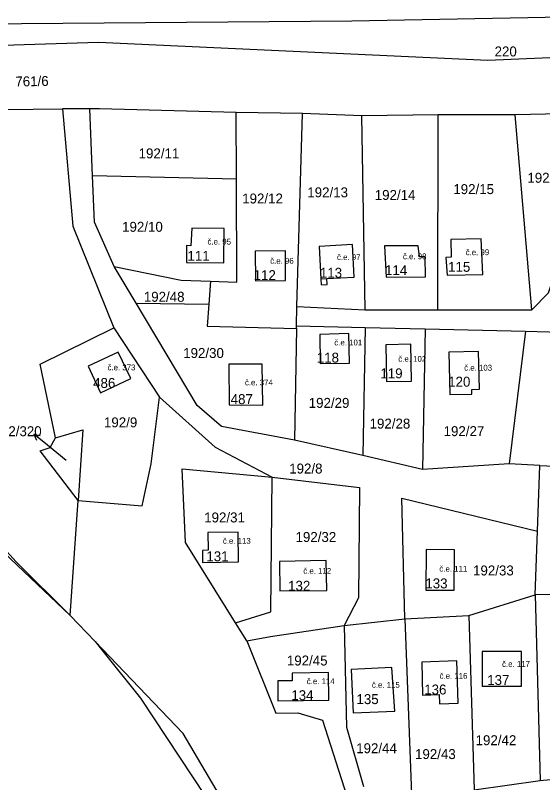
# Model space of a CAD drawing. Extents: x -887272 to -877616, y -1026687 to -1019819.
# Drawn here: x -882553.8 to -882463.7, y -1024170.3 to -1024039.2 of the extents above; entities that cross this region are included whole.
import ezdxf

# ---------------------------------------------------------------- set-up
doc = ezdxf.new("R2010")
doc.units = 0
for name, color, linetype in [('Definiční body', 7, 'Continuous'), ('Hranice parcel', 7, 'Continuous'), ('Parcelní čísla', 7, 'Continuous'), ('Polygon budovy', 7, 'Continuous'), ('Pop  PČ popisy', 7, 'Continuous'), ('Vnitřní kresba', 7, 'Continuous')]:
    doc.layers.add(name, color=color, linetype=linetype)

msp = doc.modelspace()

# ---------------------------------------------------------------- linework, layer by layer
at = {"layer": 'Hranice parcel'}
for p, q in [((-882541.07, -1024055.16), (-882545.75, -1024055.18)), ((-882545.75, -1024055.18), (-882543.98, -1024075.25)), ((-882539.38, -1024055.15), (-882541.07, -1024055.16)), ((-882540.58, -1024066.64), (-882541.07, -1024055.16)), ((-882516.06, -1024055.78), (-882539.38, -1024055.15)), ((-882516.01, -1024067.18), (-882516.06, -1024055.78)), ((-882504.74, -1024055.95), (-882516.06, -1024055.78)), ((-882505.7, -1024088.95), (-882504.74, -1024055.95)), ((-882494.61, -1024056.37), (-882504.74, -1024055.95)), ((-882481.56, -1024056.23), (-882494.61, -1024056.37)), ((-882494.01, -1024089.53), (-882494.61, -1024056.37)), ((-882481.6, -1024089.53), (-882481.56, -1024056.23)), ((-882468.38, -1024056.21), (-882481.56, -1024056.23)), ((-882459.39, -1024055.99), (-882468.38, -1024056.21)), ((-882465.58, -1024089.52), (-882468.38, -1024056.21)), ((-882516.01, -1024067.18), (-882540.58, -1024066.64)), ((-882543.98, -1024075.25), (-882536.95, -1024092.63)), ((-882533.15, -1024088.37), (-882536.9, -1024082.1)), ((-882520.44, -1024084.62), (-882520.72, -1024088.57)), ((-882533.15, -1024088.37), (-882520.72, -1024088.57)), ((-882505.74, -1024092.24), (-882505.7, -1024088.95)), ((-882505.7, -1024088.95), (-882494.01, -1024089.53)), ((-882494.01, -1024089.53), (-882481.6, -1024089.53)), ((-882481.6, -1024089.53), (-882465.58, -1024089.52)), ((-882536.95, -1024092.63), (-882529.15, -1024104.45)), ((-882505.75, -1024092.74), (-882506.08, -1024111.82)), ((-882505.75, -1024092.74), (-882505.74, -1024092.24)), ((-882505.74, -1024092.24), (-882494.04, -1024092.52)), ((-882494.04, -1024092.52), (-882494.44, -1024114.44)), ((-882494.04, -1024092.52), (-882483.75, -1024092.77)), ((-882483.75, -1024092.77), (-882484.26, -1024116.81)), ((-882483.75, -1024092.77), (-882466.65, -1024093.19)), ((-882466.65, -1024093.19), (-882469.42, -1024115.86)), ((-882466.65, -1024093.19), (-882458.6, -1024093.38)), ((-882494.44, -1024114.44), (-882506.08, -1024111.82)), ((-882543.07, -1024122.14), (-882549.54, -1024113.64)), ((-882484.26, -1024116.81), (-882494.44, -1024114.44)), ((-882469.42, -1024115.86), (-882484.26, -1024116.81)), ((-882464.18, -1024116.13), (-882469.42, -1024115.86)), ((-882464.6, -1024127.37), (-882464.18, -1024116.13)), ((-882464.18, -1024116.13), (-882447.68, -1024116.83)), ((-882544.44, -1024141.78), (-882543.07, -1024122.14)), ((-882465, -1024138.24), (-882464.6, -1024127.37)), ((-882544.44, -1024141.78), (-882553.65, -1024132.6)), ((-882476.32, -1024141.77), (-882465, -1024138.24)), ((-882453.49, -1024138.14), (-882465, -1024138.24)), ((-882465, -1024138.24), (-882464.13, -1024169.99)), ((-882544.44, -1024141.78), (-882540.14, -1024146.21)), ((-882487.23, -1024142.35), (-882476.32, -1024141.77)), ((-882476.32, -1024141.77), (-882475.42, -1024171.58)), ((-882514.25, -1024146.09), (-882516.17, -1024143.02)), ((-882497.59, -1024143.48), (-882487.23, -1024142.35)), ((-882487.23, -1024142.35), (-882486.14, -1024172.29)), ((-882508.92, -1024156.33), (-882500.23, -1024156.21)), ((-882464.13, -1024169.99), (-882453.52, -1024168.83)), ((-882475.42, -1024171.58), (-882464.13, -1024169.99))]:
    msp.add_line(p, q, dxfattribs=at)
for points in [[(-882445.26, -1024039.2), (-882496.32, -1024040.18), (-882559.82, -1024040.7), (-882602.37, -1024040.09)], [(-882603.02, -1024045.76), (-882539.56, -1024043.76), (-882473.06, -1024046.88), (-882408.1, -1024044.08), (-882339.94, -1024043.02), (-882340.1, -1024040.68)], [(-882731.42, -1024055.06), (-882680.72, -1024056.68), (-882649.26, -1024056.02), (-882607.88, -1024055.44), (-882600.66, -1024055.78), (-882545.75, -1024055.18)], [(-882465.58, -1024089.52), (-882462.72, -1024086.61), (-882455.48, -1024065.24), (-882459.39, -1024055.99)], [(-882536.9, -1024082.1), (-882540.24, -1024074.53), (-882540.58, -1024066.64)], [(-882520.44, -1024084.62), (-882515.93, -1024084.81), (-882516.01, -1024067.18)], [(-882524.56, -1024081.44), (-882518.16, -1024081.48), (-882518.1, -1024075.64), (-882523.66, -1024075.58), (-882523.8, -1024078.58), (-882524.56, -1024078.52), (-882524.56, -1024081.44)], [(-882473.94, -1024083.48), (-882474.19, -1024077.39), (-882479.39, -1024077.49), (-882479.33, -1024080.54), (-882480.23, -1024080.56), (-882480.04, -1024083.6), (-882473.94, -1024083.48)], [(-882495.9, -1024083.92), (-882496.2, -1024078.39), (-882501.88, -1024078.72), (-882501.59, -1024084.22), (-882501.54, -1024085.24), (-882500.52, -1024085.19), (-882500.58, -1024084.17), (-882495.9, -1024083.92)], [(-882490.46, -1024083.96), (-882483.72, -1024083.86), (-882483.76, -1024080.46), (-882484.76, -1024080.47), (-882485, -1024078.58), (-882490.72, -1024078.6), (-882490.46, -1024083.96)], [(-882507.66, -1024079.44), (-882512.81, -1024079.48), (-882512.77, -1024084.58), (-882507.62, -1024084.54), (-882507.66, -1024079.44)], [(-882536.9, -1024082.1), (-882525.45, -1024084.46), (-882520.44, -1024084.62)], [(-882506.08, -1024111.82), (-882518.58, -1024109.48), (-882522.71, -1024105.86), (-882533.15, -1024088.37)], [(-882520.72, -1024088.57), (-882520.99, -1024092.32), (-882505.75, -1024092.74)], [(-882546.91, -1024111.39), (-882549.52, -1024098.83), (-882536.95, -1024092.63)], [(-882501.79, -1024093.72), (-882501.71, -1024098.72), (-882496.72, -1024098.62), (-882496.79, -1024093.56), (-882501.79, -1024093.72)], [(-882490.39, -1024101.79), (-882486.14, -1024101.72), (-882486.24, -1024095.42), (-882490.49, -1024095.49), (-882490.39, -1024101.79)], [(-882534.06, -1024101.25), (-882536.19, -1024096.74), (-882541.31, -1024099.15), (-882539.22, -1024103.69), (-882534.06, -1024101.25)], [(-882479.73, -1024096.77), (-882479.54, -1024104.02), (-882475.79, -1024103.92), (-882475.81, -1024103.12), (-882474.51, -1024103.09), (-882474.68, -1024096.64), (-882479.73, -1024096.77)], [(-882511.53, -1024105.84), (-882511.6, -1024098.82), (-882517.29, -1024098.81), (-882517.24, -1024105.79), (-882511.53, -1024105.84)], [(-882543.07, -1024122.14), (-882532.14, -1024123), (-882530.59, -1024115.87), (-882529.15, -1024104.45)], [(-882529.15, -1024104.45), (-882519.64, -1024113.02), (-882509.9, -1024118.11)], [(-882546.91, -1024111.39), (-882542.24, -1024110.04), (-882543.07, -1024122.14)], [(-882549.54, -1024113.64), (-882547.84, -1024113.05), (-882546.91, -1024111.39)], [(-882553.65, -1024132.6), (-882563.04, -1024122.28), (-882568.27, -1024116.52), (-882569.89, -1024114.84), (-882570.12, -1024114.61)], [(-882570.12, -1024114.61), (-882568.22, -1024119.18), (-882544.44, -1024141.78)], [(-882516.17, -1024143.02), (-882524.72, -1024129.29), (-882525.26, -1024116.69), (-882509.9, -1024118.11)], [(-882516.17, -1024143.02), (-882510.14, -1024141.13), (-882509.9, -1024118.11)], [(-882509.9, -1024118.11), (-882495.01, -1024119.89), (-882495.16, -1024138.72), (-882497.59, -1024143.48)], [(-882487.23, -1024142.35), (-882487.75, -1024121.7), (-882464.6, -1024127.37)], [(-882520.83, -1024130.58), (-882521.83, -1024130.65), (-882521.8, -1024132.7), (-882515.65, -1024132.6), (-882515.73, -1024127.5), (-882520.88, -1024127.58), (-882520.83, -1024130.58)], [(-882478.8, -1024137.46), (-882478.76, -1024130.54), (-882483.62, -1024130.51), (-882483.66, -1024137.43), (-882478.8, -1024137.46)], [(-882500.57, -1024137.5), (-882500.66, -1024132.35), (-882508.66, -1024132.51), (-882508.62, -1024137.56), (-882500.57, -1024137.5)], [(-882514.25, -1024146.09), (-882510.19, -1024145.38), (-882497.59, -1024143.48)], [(-882497.59, -1024143.48), (-882497.2, -1024160.85), (-882494.31, -1024171)], [(-882501.82, -1024208.81), (-882505.78, -1024194.82), (-882525.14, -1024161.92), (-882540.14, -1024146.21)], [(-882540.14, -1024146.21), (-882538.86, -1024147.89), (-882532.4, -1024155.87), (-882516.84, -1024179.4), (-882505.08, -1024201.85), (-882501.82, -1024208.81)], [(-882514.25, -1024146.09), (-882509.29, -1024158.43), (-882505.52, -1024158.39), (-882501.29, -1024159.64), (-882495.81, -1024176.89), (-882492.56, -1024176.88)], [(-882474.02, -1024147.92), (-882474.02, -1024153.82), (-882467.32, -1024153.82), (-882467.32, -1024147.92), (-882474.02, -1024147.92)], [(-882484.21, -1024155.38), (-882481.36, -1024155.29), (-882481.31, -1024156.84), (-882478.16, -1024156.74), (-882478.39, -1024149.54), (-882484.36, -1024149.73), (-882484.21, -1024155.38)], [(-882496.06, -1024158.42), (-882488.94, -1024158.14), (-882489.48, -1024150.64), (-882496.4, -1024150.98), (-882496.06, -1024158.42)], [(-882500.23, -1024156.21), (-882500.29, -1024151.52), (-882506.52, -1024151.61), (-882506.5, -1024152.91), (-882508.97, -1024152.94), (-882508.92, -1024156.33)]]:
    msp.add_lwpolyline(points, dxfattribs=at)
at = {"layer": 'Polygon budovy'}
for points in [[(-882523.66, -1024075.58), (-882523.8, -1024078.58), (-882524.56, -1024078.52), (-882524.56, -1024081.44), (-882518.16, -1024081.48), (-882518.1, -1024075.64)], [(-882480.23, -1024080.56), (-882480.04, -1024083.6), (-882473.94, -1024083.48), (-882474.19, -1024077.39), (-882479.39, -1024077.49), (-882479.33, -1024080.54)], [(-882495.9, -1024083.92), (-882496.2, -1024078.39), (-882501.88, -1024078.72), (-882501.59, -1024084.22), (-882500.58, -1024084.17)], [(-882490.72, -1024078.6), (-882490.46, -1024083.96), (-882483.72, -1024083.86), (-882483.76, -1024080.46), (-882484.76, -1024080.47), (-882485, -1024078.58)], [(-882512.81, -1024079.48), (-882512.77, -1024084.58), (-882507.62, -1024084.54), (-882507.66, -1024079.44)], [(-882501.79, -1024093.72), (-882501.71, -1024098.72), (-882496.72, -1024098.62), (-882496.79, -1024093.56)], [(-882486.14, -1024101.72), (-882486.24, -1024095.42), (-882490.49, -1024095.49), (-882490.39, -1024101.79)], [(-882536.19, -1024096.74), (-882541.31, -1024099.15), (-882539.22, -1024103.69), (-882534.06, -1024101.25)], [(-882479.73, -1024096.77), (-882479.54, -1024104.02), (-882475.79, -1024103.92), (-882475.81, -1024103.12), (-882474.51, -1024103.09), (-882474.68, -1024096.64)], [(-882517.29, -1024098.81), (-882517.24, -1024105.79), (-882511.53, -1024105.84), (-882511.6, -1024098.82)], [(-882515.65, -1024132.6), (-882515.73, -1024127.5), (-882520.88, -1024127.58), (-882520.83, -1024130.58), (-882521.83, -1024130.65), (-882521.8, -1024132.7)], [(-882478.8, -1024137.46), (-882478.76, -1024130.54), (-882483.62, -1024130.51), (-882483.66, -1024137.43)], [(-882508.66, -1024132.51), (-882508.62, -1024137.56), (-882500.57, -1024137.5), (-882500.66, -1024132.35)], [(-882467.32, -1024147.92), (-882474.02, -1024147.92), (-882474.02, -1024153.82), (-882467.32, -1024153.82)], [(-882484.36, -1024149.73), (-882484.21, -1024155.38), (-882481.36, -1024155.29), (-882481.31, -1024156.84), (-882478.16, -1024156.74), (-882478.39, -1024149.54)], [(-882496.4, -1024150.98), (-882496.06, -1024158.42), (-882488.94, -1024158.14), (-882489.48, -1024150.64)], [(-882508.92, -1024156.33), (-882500.23, -1024156.21), (-882500.29, -1024151.52), (-882506.52, -1024151.61), (-882506.5, -1024152.91), (-882508.97, -1024152.94)]]:
    msp.add_lwpolyline(points, close=True, dxfattribs=at)
at = {"layer": 'Pop  PČ popisy'}
for p, q in [((-882548.31, -1024112.67), (-882550.64, -1024110.78)), ((-882550.64, -1024110.78), (-882549.55, -1024111.02)), ((-882550.64, -1024110.78), (-882550.18, -1024111.8)), ((-882545.12, -1024115.28), (-882548.31, -1024112.67))]:
    msp.add_line(p, q, dxfattribs=at)
at = {"layer": 'Vnitřní kresba'}
msp.add_line((-882501.59, -1024084.22), (-882500.58, -1024084.17), dxfattribs=at)

# ---------------------------------------------------------------- texts
at = {"layer": 'Definiční body'}
for s, p in [('č.e. 95', (-882520.96, -1024078.37)), ('č.e. 97', (-882498.83, -1024081.02)), ('č.e. 98', (-882487.57, -1024080.89)), ('č.e. 99', (-882476.86, -1024080.19)), ('č.e. 96', (-882510.25, -1024081.65)), ('č.e. 101', (-882499.29, -1024095.61)), ('č.e. 102', (-882488.36, -1024098.41)), ('č.e. 373', (-882538.03, -1024099.87)), ('č.e. 103', (-882477.11, -1024099.92)), ('č.e. 374', (-882514.56, -1024102.44)), ('č.e. 113', (-882518.33, -1024129.51)), ('č.e. 112', (-882504.59, -1024134.64)), ('č.e. 111', (-882481.35, -1024134.28)), ('č.e. 117', (-882470.64, -1024150.55)), ('č.e. 116', (-882481.32, -1024152.58)), ('č.e. 114', (-882504, -1024153.5)), ('č.e. 115', (-882492.87, -1024154.12))]:
    msp.add_text(s, height=1, dxfattribs=at).set_placement(p)
at = {"layer": 'Parcelní čísla'}
for s, p in [('220', (-882471.92, -1024046.22)), ('192/11', (-882532.72, -1024063.64)), ('192/16', (-882466.32, -1024067.81)), ('192/15', (-882478.97, -1024069.75)), ('192/12', (-882515.03, -1024071.35)), ('192/13', (-882503.91, -1024070.3)), ('192/14', (-882492.39, -1024070.75)), ('192/10', (-882535.54, -1024076.19)), ('111', (-882524.38, -1024081.15)), ('115', (-882479.86, -1024083.03)), ('112', (-882513.07, -1024084.45)), ('113', (-882501.76, -1024084.05)), ('114', (-882490.63, -1024083.6)), ('192/48', (-882531.83, -1024088.15)), ('192/30', (-882525.11, -1024097.76)), ('118', (-882502.29, -1024098.55)), ('119', (-882491.43, -1024101.24)), ('486', (-882540.49, -1024102.88)), ('120', (-882479.85, -1024102.66)), ('487', (-882517, -1024105.64)), ('192/29', (-882503.67, -1024106.28)), ('192/9', (-882538.64, -1024109.61)), ('192/28', (-882493.27, -1024109.82)), ('192/320', (-882557.5, -1024111.12)), ('192/27', (-882480.63, -1024111.11)), ('192/8', (-882507, -1024117.5)), ('192/31', (-882521.52, -1024125.86)), ('192/32', (-882505.92, -1024129.2)), ('131', (-882521.15, -1024132.5)), ('192/33', (-882475.6, -1024134.92)), ('132', (-882507.19, -1024137.54)), ('133', (-882483.75, -1024137.13)), ('192/45', (-882507.4, -1024150.31)), ('137', (-882473.18, -1024153.64)), ('136', (-882483.94, -1024155.27)), ('134', (-882506.64, -1024156.24)), ('135', (-882495.51, -1024156.91)), ('192/42', (-882475.16, -1024163.93)), ('192/44', (-882495.56, -1024165.3)), ('192/43', (-882485.51, -1024166.3))]:
    msp.add_text(s, height=1.7, dxfattribs=at).set_placement(p)
msp.add_text('761/6', height=1.7, rotation=1, dxfattribs=at).set_placement((-882553.76, -1024051.36))

doc.saveas('drawing.dxf')
